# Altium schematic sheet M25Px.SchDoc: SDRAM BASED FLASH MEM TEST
size A4; Engineer: SHOWELL; DocumentNumber: 1; Revision: 1.00; SheetNumber: 1; SheetTotal: 1
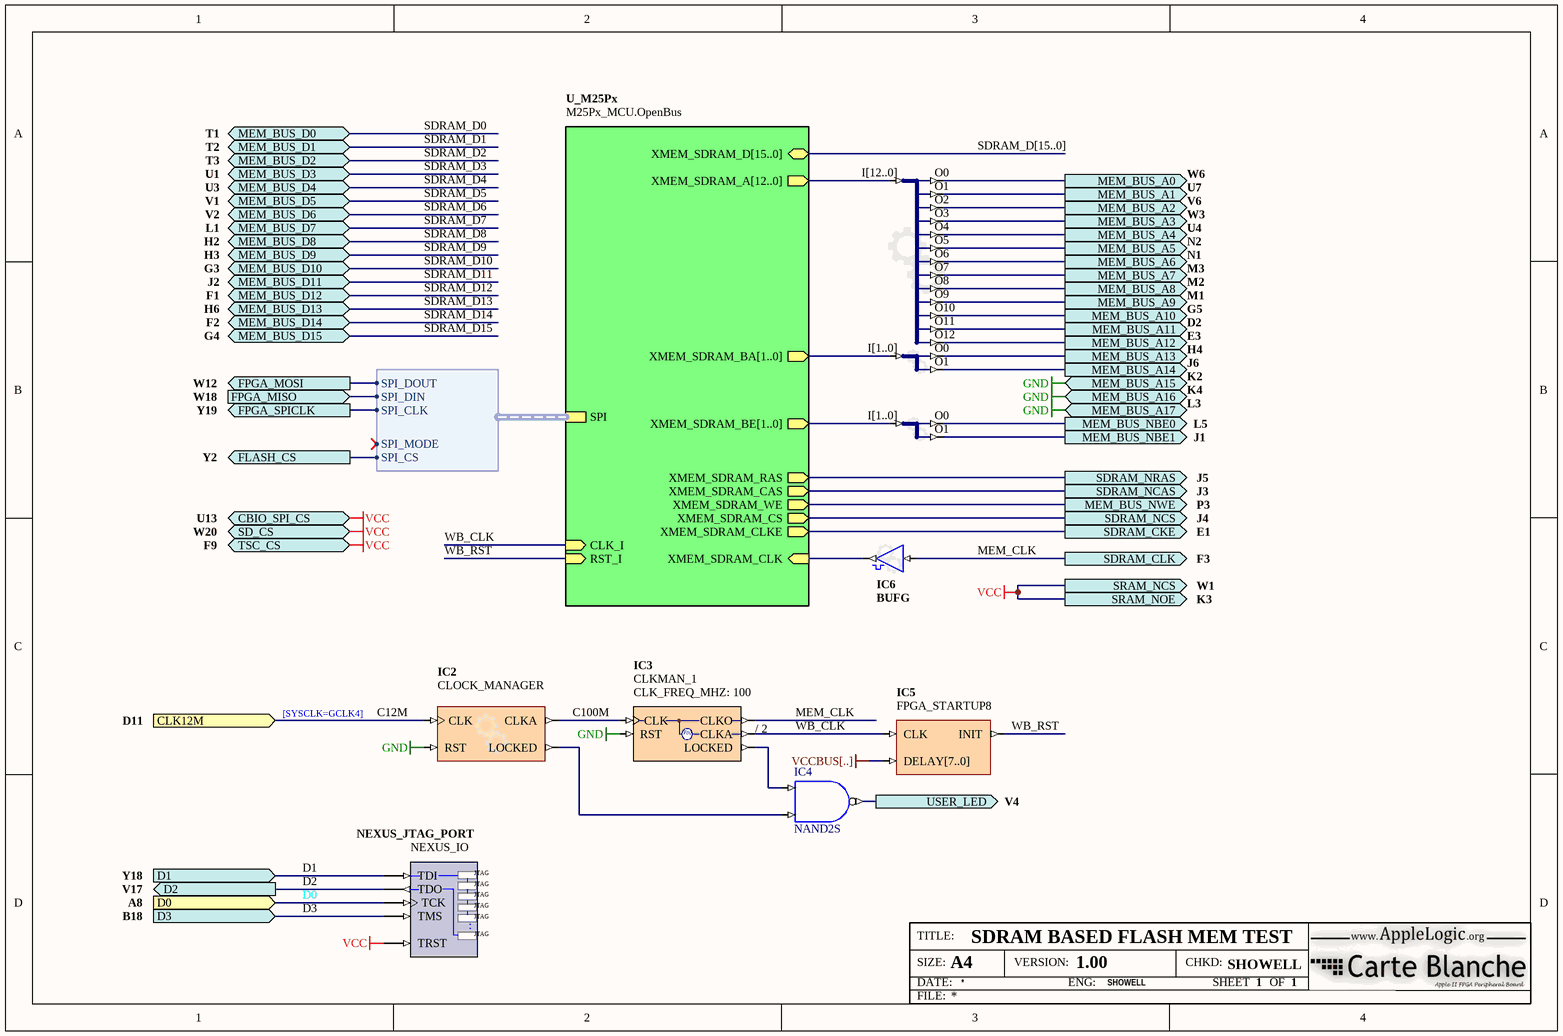
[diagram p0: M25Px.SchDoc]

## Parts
IC2  CLOCK_MANAGER
IC3  CLKMAN_1  CLK_FREQ_MHZ: 100  ClkA_Operation: / 2
IC4  NAND2S
IC5  FPGA_STARTUP8
IC6  BUFG
NEXUS_JTAG_PORT  NEXUS_IO
U1011  BUS_JS  (value not drawn)
U1018  BUS_JS  (value not drawn)
U8011  BUS_JS  (value not drawn)

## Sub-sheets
U_M25Px = M25Px_MCU.OpenBus: XMEM_SDRAM_D[15..0] (bidir), XMEM_SDRAM_A[12..0] (out), XMEM_SDRAM_BA[1..0] (out), XMEM_SDRAM_BE[1..0] (out), XMEM_SDRAM_RAS (out), XMEM_SDRAM_CAS (out), XMEM_SDRAM_WE (out), XMEM_SDRAM_CS (out), XMEM_SDRAM_CLKE (out), XMEM_SDRAM_CLK (in), SPI (harness SPI_W_NB), RST_I (in), CLK_I (in)

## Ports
CBIO_SPI_CS (out, see U13), CLK12M (in, see D11), D0 (in, see A8), D1 (in, see Y18), D2 (out, see V17), D3 (in, see B18), FLASH_CS (out, see Y2), FPGA_MISO (in, see W18), FPGA_MOSI (out, see W12), FPGA_SPICLK (out, see Y19), MEM_BUS_A0 (out, see W6), MEM_BUS_A1 (out, see U7), MEM_BUS_A2 (out, see V6), MEM_BUS_A3 (out, see W3), MEM_BUS_A4 (out, see U4), MEM_BUS_A5 (out, see N2), MEM_BUS_A6 (out, see N1), MEM_BUS_A7 (out, see M3), MEM_BUS_A8 (out, see M2), MEM_BUS_A9 (out, see M1), MEM_BUS_A10 (out, see G5), MEM_BUS_A11 (out, see D2), MEM_BUS_A12 (out, see E3), MEM_BUS_A13 (out, see H4), MEM_BUS_A14 (out, see J6), MEM_BUS_A15 (out, see K2), MEM_BUS_A16 (out, see K4), MEM_BUS_A17 (out, see L3), MEM_BUS_D0 (bidir, see T1), MEM_BUS_D1 (bidir, see T2), MEM_BUS_D2 (bidir, see T3), MEM_BUS_D3 (bidir, see U1), MEM_BUS_D4 (bidir, see U3), MEM_BUS_D5 (bidir, see V1), MEM_BUS_D6 (bidir, see V2), MEM_BUS_D7 (bidir, see L1), MEM_BUS_D8 (bidir, see H2), MEM_BUS_D9 (bidir, see H3), MEM_BUS_D10 (bidir, see G3), MEM_BUS_D11 (bidir, see J2), MEM_BUS_D12 (bidir, see F1), MEM_BUS_D13 (bidir, see H6), MEM_BUS_D14 (bidir, see F2), MEM_BUS_D15 (bidir, see G4), MEM_BUS_NBE0 (out, see L5), MEM_BUS_NBE1 (out, see J1), MEM_BUS_NWE (out, see P3), SD_CS (out, see W20), SDRAM_CKE (out, see E1), SDRAM_CLK (out, see F3), SDRAM_NCAS (out, see J3), SDRAM_NCS (out, see J4), SDRAM_NRAS (out, see J5), SRAM_NCS (out, see W1), SRAM_NOE (out, see K3), TSC_CS (out, see F9), USER_LED (out, see V4)

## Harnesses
SPI_W_NB: SPI_DOUT, SPI_DIN, SPI_CLK, SPI_MODE, SPI_CS

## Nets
GND: IC2.RST IC3.RST ; port MEM_BUS_A15, port MEM_BUS_A16, port MEM_BUS_A17
VCC: NEXUS_JTAG_PORT.TRST ; port SRAM_NOE, port SRAM_NCS, port TSC_CS, port CBIO_SPI_CS, port SD_CS
C12M: IC2.CLK ; port CLK12M
C100M: IC2.CLKA IC3.CLK
D0: NEXUS_JTAG_PORT.TCK ; port D0
D1: NEXUS_JTAG_PORT.TDI ; port D1
D2: NEXUS_JTAG_PORT.TDO ; port D2
D3: NEXUS_JTAG_PORT.TMS ; port D3
FLASH_CS: port FLASH_CS, sheet U_M25Px/SPI.SPI_CS
FPGA_MISO: port FPGA_MISO, sheet U_M25Px/SPI.SPI_DIN
FPGA_MOSI: port FPGA_MOSI, sheet U_M25Px/SPI.SPI_DOUT
FPGA_SPICLK: port FPGA_SPICLK, sheet U_M25Px/SPI.SPI_CLK
MEM_BUS_A0: U1018.O0 ; port MEM_BUS_A0
MEM_BUS_A1: U1018.O1 ; port MEM_BUS_A1
MEM_BUS_A2: U1018.O2 ; port MEM_BUS_A2
MEM_BUS_A3: U1018.O3 ; port MEM_BUS_A3
MEM_BUS_A4: U1018.O4 ; port MEM_BUS_A4
MEM_BUS_A5: U1018.O5 ; port MEM_BUS_A5
MEM_BUS_A6: U1018.O6 ; port MEM_BUS_A6
MEM_BUS_A7: U1018.O7 ; port MEM_BUS_A7
MEM_BUS_A8: U1018.O8 ; port MEM_BUS_A8
MEM_BUS_A9: U1018.O9 ; port MEM_BUS_A9
MEM_BUS_A10: U1018.O10 ; port MEM_BUS_A10
MEM_BUS_A11: U1018.O11 ; port MEM_BUS_A11
MEM_BUS_A12: U1018.O12 ; port MEM_BUS_A12
MEM_BUS_A13: U8011.O0 ; port MEM_BUS_A13
MEM_BUS_A14: U8011.O1 ; port MEM_BUS_A14
MEM_BUS_NBE0: U1011.O0 ; port MEM_BUS_NBE0
MEM_BUS_NBE1: U1011.O1 ; port MEM_BUS_NBE1
MEM_BUS_NWE: port MEM_BUS_NWE, sheet U_M25Px/XMEM_SDRAM_WE
MEM_CLK: IC3.CLKO IC6.I ; port SDRAM_CLK
SDRAM_CKE: port SDRAM_CKE, sheet U_M25Px/XMEM_SDRAM_CLKE
SDRAM_NCAS: port SDRAM_NCAS, sheet U_M25Px/XMEM_SDRAM_CAS
SDRAM_NCS: port SDRAM_NCS, sheet U_M25Px/XMEM_SDRAM_CS
SDRAM_NRAS: port SDRAM_NRAS, sheet U_M25Px/XMEM_SDRAM_RAS
USER_LED: IC4.O ; port USER_LED
WB_CLK: IC3.CLKA IC5.CLK ; sheet U_M25Px/CLK_I
WB_RST: IC5.INIT ; sheet U_M25Px/RST_I
NetIC2_LOCKED: IC2.LOCKED IC4.I0
NetIC3_LOCKED: IC3.LOCKED IC4.I1
NetIC6_O: IC6.O ; sheet U_M25Px/XMEM_SDRAM_CLK

Not connected (* = marked no-connect by the designer): IC5 DELAY[7..0]; U1011 I[1..0]; U1018 I[12..0]; U8011 I[1..0]

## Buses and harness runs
bus SDRAM_D[15..0] = sheet U_M25Px/XMEM_SDRAM_D[15..0]

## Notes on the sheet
- [SYSCLK=GCLK4]
- Labels drawn without touching a wire or pin: VCCBUS[..]

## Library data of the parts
IC2 = CLOCKMANAGER: Configurable Clock Manager; ConfiguratorName: GENERIC_CLOCKMANAGER; ConfigurationParameters: {}Version[1.0]{}Option_Configuration[object _1: TClockManagerPersist / VersionMajor [ 0 / VersionMinor [ 0 / InputFreq [ 24.000000000000000000 / InputName [ 'CLK' / OutputTargets [ < / item / Name [ 'CLKA' / OutFreqMin [ 200.000000000000000000 / OutFreqMax [ 200.000000000000000000 / OutPostDivider [ 1.000000000000000000 / end> / OutputDevices [ < / item / Name [ 'Spartan3AN' / Valid [ True / OutputActuals [ < / item / Name [ 'CLK0' / Multipler [ 1.000000000000000000 / Divider [ 1.000000000000000000 / OutFreq [ 24.000000000000000000 / OutputMap [ 1 / end / item / Name [ 'CLK90' / Multipler [ 1.000000000000000000 / Divider [ 1.000000000000000000 / OutPhase [ 90.000000000000000000 / OutFreq [ 24.000000000000000000 / OutputMap [ 2 / end / item / Name [ 'CLK180' / Multipler [ 1.000000000000000000 / Divider [ 1.000000000000000000 / OutPhase [ 180.000000000000000000 / OutFreq [ 24.000000000000000000 / OutputMap [ 3 / end / item / Name [ 'CLK270' / Multipler [ 1.000000000000000000 / Divider [ 1.000000000000000000 / OutPhase [ 270.000000000000000000 / OutFreq [ 24.000000000000000000 / OutputMap [ 4 / end / item / Name [ 'CLK2X' / Multipler [ 2.000000000000000000 / Divider [ 1.000000000000000000 / OutFreq [ 48.000000000000000000 / OutputMap [ 5 / end / item / Name [ 'CLKDV' / Multipler [ 1.000000000000000000 / Divider [ 16.000000000000000000 / OutFreq [ 1.500000000000000000 / OutputMap [ 6 / end / item / Name [ 'CLK2X180' / Multipler [ 1.000000000000000000 / Divider [ 1.000000000000000000 / OutPhase [ 180.000000000000000000 / OutFreq [ 48.000000000000000000 / OutputMap [ 7 / end / item / Name [ 'CLKFX' / Multipler [ 25.000000000000000000 / Divider [ 3.000000000000000000 / OutFreq [ 200.000000000000000000 / OutputMap [ 0 / end / item / Name [ 'CLKFX180' / Multipler [ 1.000000000000000000 / Divider [ 1.000000000000000000 / OutPhase [ 180.000000000000000000 / OutFreq [ 200.000000000000000000 / OutputMap [ 8 / end> / InternalActuals [ <> / CustomVars [ <> / end> / MinInputFreq [ 1.000000000000000000 / MaxInputFreq [ 280.000000000000000000 / MinOutputFreq [ 18.000000000000000000 / MaxOutputFreq [ 210.000000000000000000 / MaxOutputCount [ 9 / end]{}
IC3 = CLKMAN_1: Single Operational Output Clock Manager; Clk_Count: 1
IC4 = NAND2: 2-Input NAND Gate, Single Pin Version; ArchiveName: GENERIC; XilinxEquivalent: NAND2; FunctionalClass: Logic Primitive; PortSize: 2; VHDLIB_SIM: GENERIC_LIB
IC5 = FPGA_STARTUP8: FPGA Startup With 8 Bit Delay
IC6 = BUFG: Configurable Global Clock Buffer; ConfiguratorName: GENERIC_BUFFER; ConfigurationParameters: {}Version[1.1]{}SignalCount[1]{}SignalWidth0[1]{}OutputOption0[Global Clock]{}EnableMode[None]{}ShowPinNames[False]{}
NEXUS_JTAG_PORT = NEXUS_JTAG_PORT: Soft Nexus-Chain Connector; NEXUS_JTAG_CONNECTOR: True
U1011 U8011 = BUS_JS: Configurable Bus Joiner/Splitter; ConfiguratorName: GENERIC_BUS_JS; ConfigurationParameters: {}Version[1.1]{}SplitterJoinerType[Splitter]{}SignalCount[2]{}SignalWidth0[1]{}GapBelow0[1000000]{}ConnectionType0[Pin]{}SignalWidth1[1]{}GapBelow1[1000000]{}ConnectionType1[Pin]{}ShowPinNames[True]{}
U1018 = BUS_JS: Configurable Bus Joiner/Splitter; ConfiguratorName: GENERIC_BUS_JS; ConfigurationParameters: {}Version[1.1]{}SplitterJoinerType[Splitter]{}SignalCount[13]{}SignalWidth0[1]{}GapBelow0[1000000]{}ConnectionType0[Pin]{}SignalWidth1[1]{}GapBelow1[1000000]{}ConnectionType1[Pin]{}SignalWidth2[1]{}GapBelow2[1000000]{}ConnectionType2[Pin]{}SignalWidth3[1]{}GapBelow3[1000000]{}ConnectionType3[Pin]{}SignalWidth4[1]{}GapBelow4[1000000]{}ConnectionType4[Pin]{}SignalWidth5[1]{}GapBelow5[1000000]{}ConnectionType5[Pin]{}SignalWidth6[1]{}GapBelow6[1000000]{}ConnectionType6[Pin]{}SignalWidth7[1]{}GapBelow7[1000000]{}ConnectionType7[Pin]{}SignalWidth8[1]{}GapBelow8[1000000]{}ConnectionType8[Pin]{}SignalWidth9[1]{}GapBelow9[1000000]{}ConnectionType9[Pin]{}SignalWidth10[1]{}GapBelow10[1000000]{}ConnectionType10[Pin]{}SignalWidth11[1]{}GapBelow11[1000000]{}ConnectionType11[Pin]{}SignalWidth12[1]{}GapBelow12[1000000]{}ConnectionType12[Pin]{}ShowPinNames[True]{}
